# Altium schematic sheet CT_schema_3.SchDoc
size 288 x 169 mm
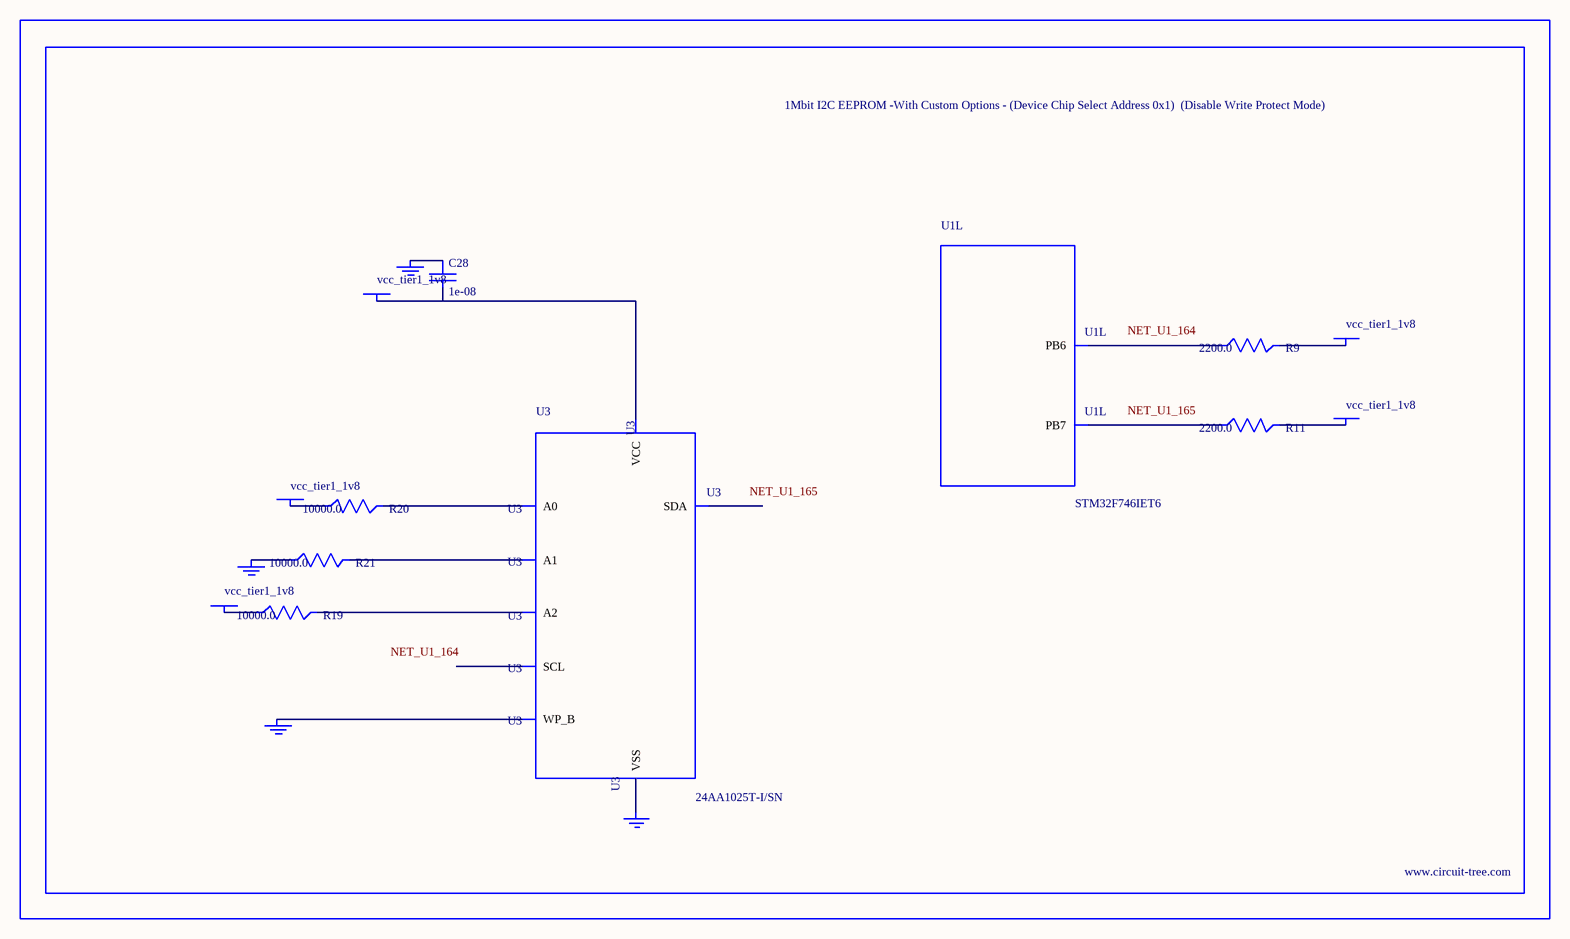
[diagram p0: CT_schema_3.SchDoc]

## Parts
BORDER2  (no value)
C28  1e-08  [C0402]
GND_INSTANCE_2_0  (no value)
GND_INSTANCE_2_1  (no value)
GND_INSTANCE_2_2  (no value)
GND_INSTANCE_2_3  (no value)
POWER_INSTANCE_2_0  vcc_tier1_1v8
POWER_INSTANCE_2_1  vcc_tier1_1v8
POWER_INSTANCE_2_2  vcc_tier1_1v8
POWER_INSTANCE_2_3  vcc_tier1_1v8
POWER_INSTANCE_2_4  vcc_tier1_1v8
R9  2200.0  [R0603]
R11  2200.0  [R0603]
R19  10000.0  [R0603]
R20  10000.0  [R0603]
R21  10000.0  [R0603]
U1  STM32F746IET6  [LQFP176]  (part L of 12)
U3  24AA1025T-I/SN  [SOIC-8]

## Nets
NetC28_1: C28.1 GND_INSTANCE_2_2.0(GND)
NetC28_2: C28.2 POWER_INSTANCE_2_2.0(PWR) U3.8(VCC)
NetGND_INSTANCE_2_0_0: GND_INSTANCE_2_0.0(GND) R21.1
NetGND_INSTANCE_2_1_0: GND_INSTANCE_2_1.0(GND) U3.7(WP_B)
NetGND_INSTANCE_2_3_0: GND_INSTANCE_2_3.0(GND) U3.4(VSS)
NetPOWER_INSTANCE_2_0_0: POWER_INSTANCE_2_0.0(PWR) R20.1
NetPOWER_INSTANCE_2_1_0: POWER_INSTANCE_2_1.0(PWR) R19.1
NetPOWER_INSTANCE_2_3_0: POWER_INSTANCE_2_3.0(PWR) R9.2
NetPOWER_INSTANCE_2_4_0: POWER_INSTANCE_2_4.0(PWR) R11.2
NetR9_1: R9.1 U1.164(PB6)
NetR11_1: R11.1 U1.165(PB7)
NetR19_2: R19.2 U3.3(A2)
NetR20_2: R20.2 U3.1(A0)
NetR21_2: R21.2 U3.2(A1)

Not connected (* = marked no-connect by the designer): U3 5(SDA) 6(SCL)

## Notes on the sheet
- Labels drawn without touching a wire or pin: NET_U1_164, NET_U1_165

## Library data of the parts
BORDER2 = BORDER_PAGE2
C28 = C0402C103K3RAC
GND_INSTANCE_2_0-GND_INSTANCE_2_3 = GND
POWER_INSTANCE_2_0-POWER_INSTANCE_2_4 = PWR
R9 R11 = RC0603JR-072K2L
R19-R21 = RC0603JR-0710KL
